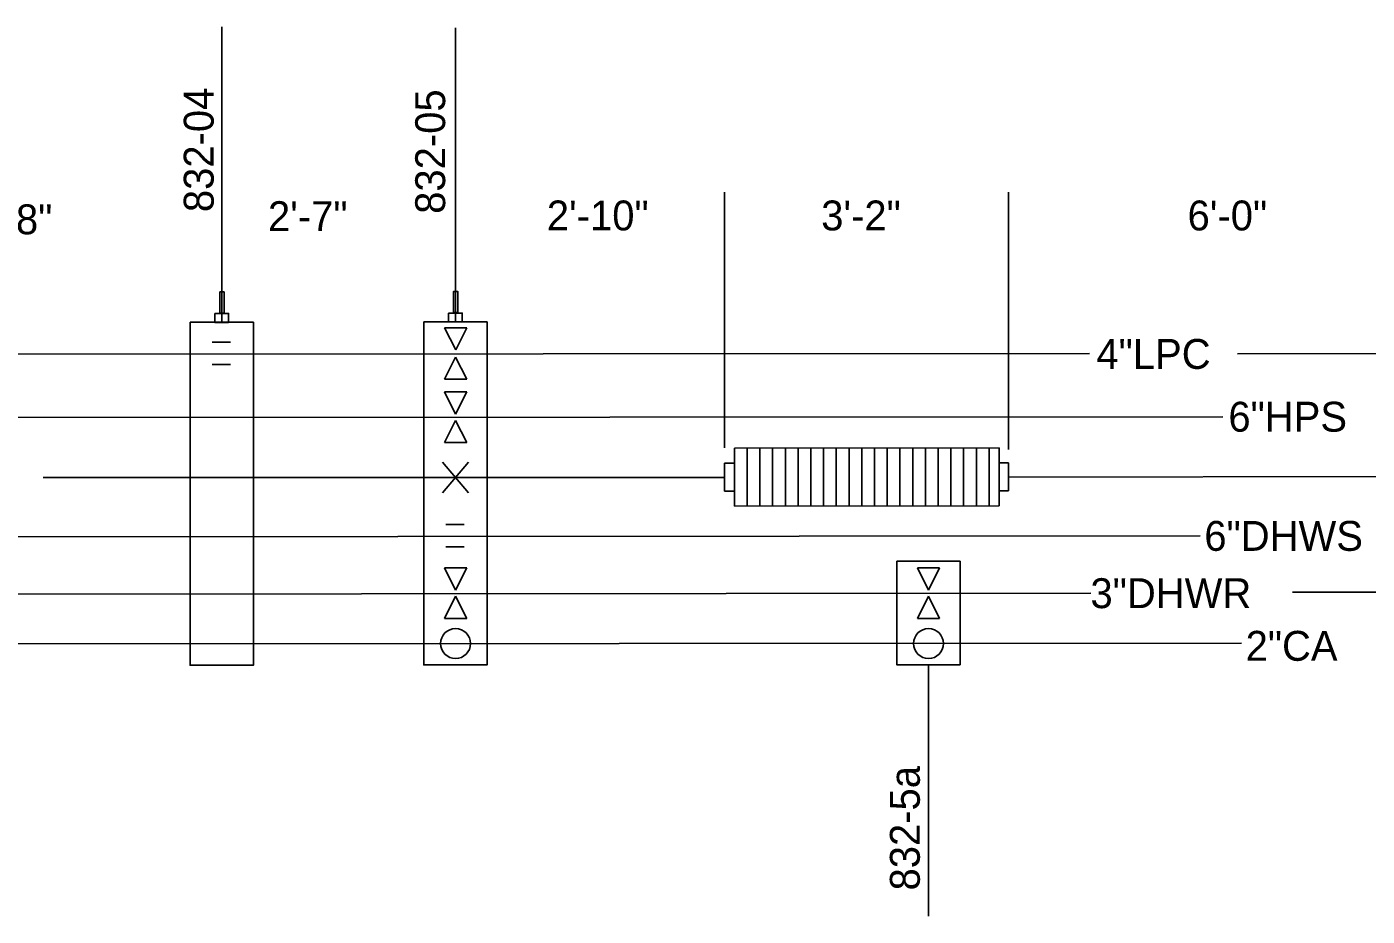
# Model space of a CAD drawing. Extents: x 9888 to 10178, y 10284 to 10314.
# Drawn here: x 9960.12 to 9975.06, y 10285.84 to 10295.75 of the extents above; entities that cross this region are included whole.
import ezdxf

# ---------------------------------------------------------------- set-up
doc = ezdxf.new("R2010")
doc.units = 0
for name, color, linetype in [('Level 51', 7, 'Continuous'), ('M-EQPM-N', 7, 'Continuous'), ('M-STEM-CONP', 7, 'Continuous'), ('M-STEM-CONP-N', 7, 'Continuous'), ('P-CMPA-PIPE', 7, 'Continuous'), ('P-CMPA-PIPE-N', 7, 'Continuous'), ('P-DOMW-HPIP-N', 7, 'Continuous')]:
    doc.layers.add(name, color=color, linetype=linetype)

msp = doc.modelspace()

# ---------------------------------------------------------------- linework, layer by layer
at = {"layer": 'Level 51'}
for p, q in [((9964.898, 10292.151), (9964.774, 10292.399)), ((9964.774, 10292.399), (9965.022, 10292.399)), ((9964.898, 10292.151), (9965.022, 10292.399)), ((9962.184, 10292.237), (9962.388, 10292.237)), ((9973.612, 10292.107), (10036.2, 10292.214)), ((9956.292, 10292.101), (9971.96, 10292.111)), ((9964.896, 10292.072), (9964.772, 10291.824)), ((9964.896, 10292.072), (9965.02, 10291.824)), ((9962.184, 10291.987), (9962.388, 10291.987)), ((9964.772, 10291.824), (9965.02, 10291.824))]:
    msp.add_line(p, q, dxfattribs=at)
at = {"layer": 'M-EQPM-N'}
for p, q in [((9962.29, 10292.46), (9962.29, 10295.754)), ((9964.895, 10292.463), (9964.895, 10295.742)), ((9967.893, 10291.058), (9967.893, 10293.91)), ((9971.06, 10291.042), (9971.06, 10293.91)), ((9970.166, 10285.837), (9970.166, 10288.639))]:
    msp.add_line(p, q, dxfattribs=at)
for points in [[(9961.938, 10292.46), (9962.643, 10292.46), (9962.643, 10288.636), (9961.938, 10288.636)], [(9964.542, 10292.463), (9965.247, 10292.463), (9965.247, 10288.639), (9964.542, 10288.639)], [(9970.519, 10288.639), (9969.814, 10288.639), (9969.814, 10289.794), (9970.519, 10289.794)]]:
    msp.add_lwpolyline(points, close=True, dxfattribs=at)
at = {"layer": 'M-STEM-CONP'}
for p, q in [((9964.896, 10291.435), (9964.772, 10291.683)), ((9964.772, 10291.683), (9965.02, 10291.683)), ((9964.896, 10291.435), (9965.02, 10291.683)), ((9948.22, 10291.388), (9973.447, 10291.406)), ((9964.896, 10291.365), (9964.772, 10291.118)), ((9964.896, 10291.365), (9965.02, 10291.118)), ((9964.772, 10291.118), (9965.02, 10291.118))]:
    msp.add_line(p, q, dxfattribs=at)
at = {"layer": 'M-STEM-CONP-N'}
for p, q in [((9970.953, 10291.059), (9968.004, 10291.056)), ((9968.004, 10291.056), (9968.004, 10290.41)), ((9968.146, 10291.056), (9968.146, 10290.41)), ((9968.288, 10291.056), (9968.288, 10290.41)), ((9968.43, 10291.056), (9968.43, 10290.41)), ((9968.572, 10291.056), (9968.572, 10290.41)), ((9968.714, 10291.056), (9968.714, 10290.41)), ((9968.856, 10291.056), (9968.856, 10290.41)), ((9968.997, 10291.056), (9968.997, 10290.41)), ((9969.139, 10291.056), (9969.139, 10290.41)), ((9969.281, 10291.056), (9969.281, 10290.41)), ((9969.423, 10291.056), (9969.423, 10290.41)), ((9969.565, 10291.056), (9969.565, 10290.41)), ((9969.707, 10291.056), (9969.707, 10290.41)), ((9969.849, 10291.056), (9969.849, 10290.41)), ((9969.991, 10291.056), (9969.991, 10290.41)), ((9970.133, 10291.056), (9970.133, 10290.41)), ((9970.274, 10291.056), (9970.274, 10290.41)), ((9970.416, 10291.056), (9970.416, 10290.41)), ((9970.558, 10291.056), (9970.558, 10290.41)), ((9970.7, 10291.056), (9970.7, 10290.41)), ((9970.842, 10291.056), (9970.842, 10290.41)), ((9970.953, 10291.059), (9970.953, 10290.413)), ((9964.749, 10290.558), (9965.04, 10290.898)), ((9964.749, 10290.898), (9965.04, 10290.558)), ((9967.893, 10290.576), (9967.893, 10290.89)), ((9967.893, 10290.89), (9968.001, 10290.89)), ((9970.953, 10290.893), (9971.06, 10290.893)), ((9971.06, 10290.579), (9971.06, 10290.893)), ((9960.3, 10290.727), (9967.893, 10290.73)), ((9971.06, 10290.733), (10036.349, 10290.833)), ((9968.001, 10290.576), (9967.893, 10290.576)), ((9971.06, 10290.579), (9970.953, 10290.579)), ((9970.953, 10290.413), (9968.004, 10290.41))]:
    msp.add_line(p, q, dxfattribs=at)
at = {"layer": 'P-CMPA-PIPE'}
for points in [[(9962.27, 10292.563), (9962.317, 10292.563), (9962.317, 10292.798), (9962.27, 10292.798)], [(9964.874, 10292.567), (9964.921, 10292.567), (9964.921, 10292.803), (9964.874, 10292.803)], [(9962.214, 10292.559), (9962.367, 10292.559), (9962.367, 10292.459), (9962.214, 10292.459)], [(9964.818, 10292.563), (9964.971, 10292.563), (9964.971, 10292.463), (9964.818, 10292.463)]]:
    msp.add_lwpolyline(points, close=True, dxfattribs=at)
at = {"layer": 'P-CMPA-PIPE-N'}
msp.add_line((9951.679, 10288.868), (9973.655, 10288.882), dxfattribs=at)
for centre in [(9964.896, 10288.877), (9970.167, 10288.877)]:
    msp.add_circle(centre, 0.167, dxfattribs=at)
at = {"layer": 'P-DOMW-HPIP-N'}
for p, q in [((9964.788, 10290.206), (9964.992, 10290.206)), ((9955.621, 10290.065), (9973.196, 10290.077)), ((9964.788, 10289.956), (9964.992, 10289.956)), ((9964.896, 10289.474), (9964.772, 10289.722)), ((9964.772, 10289.722), (9965.02, 10289.722)), ((9964.896, 10289.474), (9965.02, 10289.722)), ((9970.168, 10289.474), (9970.044, 10289.722)), ((9970.044, 10289.722), (9970.291, 10289.722)), ((9970.168, 10289.474), (9970.291, 10289.722)), ((9948.766, 10289.421), (9971.976, 10289.438)), ((9964.896, 10289.404), (9964.772, 10289.157)), ((9964.896, 10289.404), (9965.02, 10289.157)), ((9970.168, 10289.404), (9970.044, 10289.157)), ((9970.168, 10289.404), (9970.291, 10289.157)), ((9974.223, 10289.45), (9989.896, 10289.47)), ((9964.772, 10289.157), (9965.02, 10289.157)), ((9970.044, 10289.157), (9970.291, 10289.157))]:
    msp.add_line(p, q, dxfattribs=at)

# ---------------------------------------------------------------- texts
at = {"layer": 'Level 51'}
msp.add_text('4"LPC', height=0.3333, dxfattribs=at).set_placement((9972.038, 10291.94))
at = {"layer": 'M-EQPM-N'}
for s, p in [('832-04', (9962.2, 10293.688)), ('832-05', (9964.78, 10293.669)), ('832-5a', (9970.07, 10286.124))]:
    msp.add_text(s, height=0.3333, rotation=90, dxfattribs=at).set_placement(p)
for s, p in [('4\'-8"', (9959.515, 10293.441)), ('2\'-7"', (9962.805, 10293.476)), ('2\'-10"', (9965.913, 10293.484)), ('3\'-2"', (9968.971, 10293.484)), ('6\'-0"', (9973.054, 10293.484))]:
    msp.add_text(s, height=0.3333, dxfattribs=at).set_placement(p)
at = {"layer": 'M-STEM-CONP'}
msp.add_text('6"HPS', height=0.3333, dxfattribs=at).set_placement((9973.509, 10291.24))
at = {"layer": 'P-CMPA-PIPE'}
msp.add_text('2"CA', height=0.3333, dxfattribs=at).set_placement((9973.701, 10288.685))
at = {"layer": 'P-DOMW-HPIP-N'}
for s, p in [('6"DHWS', (9973.241, 10289.911)), ('3"DHWR', (9971.972, 10289.272))]:
    msp.add_text(s, height=0.3333, dxfattribs=at).set_placement(p)

doc.saveas('drawing.dxf')
